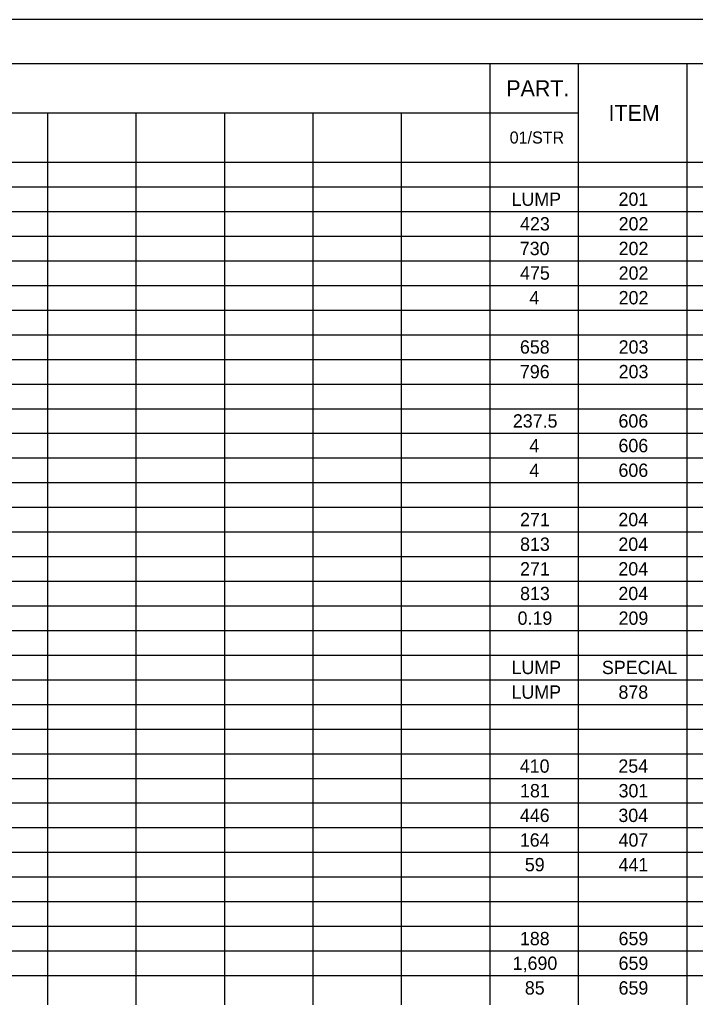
# Model space of a CAD drawing. Extents: x -98 to 34, y 0 to 58.
# Drawn here: x 9.22 to 16.9, y 10.89 to 22 of the extents above; entities that cross this region are included whole.
import ezdxf

# ---------------------------------------------------------------- set-up
doc = ezdxf.new("R2010")
doc.units = 0
for name, color, linetype in [('Default', 7, 'Continuous'), ('SH_Border', 7, 'Continuous'), ('SH_Cut_Line', 7, 'Continuous')]:
    doc.layers.add(name, color=color, linetype=linetype)

msp = doc.modelspace()

# ---------------------------------------------------------------- linework, layer by layer
at = {"layer": 'Default'}
for p, q in [((1.5, 21.5), (32, 21.5)), ((14.56, 21.5), (14.56, 0.502)), ((15.564, 21.5), (15.564, 0.502)), ((16.799, 21.5), (16.799, 0.502)), ((1.5, 20.94), (15.564, 20.94)), ((9.537, 20.94), (9.537, 0.502)), ((10.541, 20.94), (10.541, 0.502)), ((11.546, 20.94), (11.546, 0.502)), ((12.55, 20.94), (12.55, 0.502)), ((13.555, 20.94), (13.555, 0.502)), ((1.5, 20.38), (32, 20.38)), ((1.5, 20.1), (32, 20.1)), ((1.5, 19.82), (32, 19.82)), ((1.5, 19.54), (32, 19.54)), ((1.5, 19.26), (32, 19.26)), ((1.5, 18.98), (32, 18.98)), ((1.5, 18.7), (32, 18.7)), ((1.5, 18.42), (32, 18.42)), ((1.5, 18.14), (32, 18.14)), ((1.5, 17.86), (32, 17.86)), ((1.5, 17.58), (32, 17.58)), ((1.5, 17.3), (32, 17.3)), ((1.5, 17.021), (32, 17.021)), ((1.5, 16.741), (32, 16.741)), ((1.5, 16.461), (32, 16.461)), ((1.5, 16.181), (32, 16.181)), ((1.5, 15.901), (32, 15.901)), ((1.5, 15.621), (32, 15.621)), ((1.5, 15.341), (32, 15.341)), ((1.5, 15.061), (32, 15.061)), ((1.5, 14.781), (32, 14.781)), ((1.5, 14.501), (32, 14.501)), ((1.5, 14.221), (32, 14.221)), ((1.5, 13.941), (32, 13.941)), ((1.5, 13.661), (32, 13.661)), ((1.5, 13.381), (32, 13.381)), ((1.5, 13.101), (32, 13.101)), ((1.5, 12.821), (32, 12.821)), ((1.5, 12.541), (32, 12.541)), ((1.5, 12.261), (32, 12.261)), ((1.5, 11.981), (32, 11.981)), ((1.5, 11.701), (32, 11.701)), ((1.5, 11.421), (32, 11.421)), ((1.5, 11.141), (32, 11.141))]:
    msp.add_line(p, q, dxfattribs=at)
at = {"layer": 'SH_Border'}
msp.add_lwpolyline([(1.5, 21.5), (33.5, 21.5), (33.5, 0.5), (1.5, 0.5)], close=True, dxfattribs=at)
at = {"layer": 'SH_Cut_Line'}
msp.add_lwpolyline([(0, 0), (34, 0), (34, 22), (0, 22)], close=True, dxfattribs=at)

# ---------------------------------------------------------------- texts
at = {"layer": 'Default'}
for s, height, p in [('PART.', 0.1818, (14.749, 21.129)), ('ITEM', 0.1818, (15.91, 20.849)), ('01/STR', 0.1364, (14.787, 20.592)), ('LUMP', 0.1515, (14.808, 19.884)), ('201', 0.1515, (16.024, 19.884)), ('423', 0.1515, (14.905, 19.604)), ('202', 0.1515, (16.025, 19.604)), ('730', 0.1515, (14.902, 19.324)), ('202', 0.1515, (16.025, 19.324)), ('475', 0.1515, (14.905, 19.045)), ('202', 0.1515, (16.025, 19.045)), ('4', 0.152, (15.011, 18.765)), ('202', 0.1515, (16.025, 18.765)), ('658', 0.1515, (14.903, 18.205)), ('203', 0.1515, (16.025, 18.205)), ('796', 0.1515, (14.903, 17.925)), ('203', 0.1515, (16.025, 17.925)), ('237.5', 0.1515, (14.823, 17.365)), ('606', 0.1515, (16.023, 17.365)), ('4', 0.152, (15.011, 17.085)), ('606', 0.1515, (16.023, 17.085)), ('4', 0.152, (15.011, 16.805)), ('606', 0.1515, (16.023, 16.805)), ('271', 0.1515, (14.905, 16.245)), ('204', 0.1515, (16.022, 16.245)), ('813', 0.1515, (14.905, 15.965)), ('204', 0.1515, (16.022, 15.965)), ('271', 0.1515, (14.905, 15.685)), ('204', 0.1515, (16.022, 15.685)), ('813', 0.1515, (14.905, 15.405)), ('204', 0.1515, (16.022, 15.405)), ('0.19', 0.1515, (14.877, 15.125)), ('209', 0.1515, (16.024, 15.125)), ('LUMP', 0.1515, (14.808, 14.565)), ('SPECIAL', 0.1515, (15.835, 14.565)), ('LUMP', 0.1515, (14.808, 14.285)), ('878', 0.1515, (16.023, 14.285)), ('410', 0.1515, (14.902, 13.445)), ('254', 0.1515, (16.022, 13.445)), ('181', 0.1515, (14.905, 13.165)), ('301', 0.1515, (16.024, 13.165)), ('446', 0.1515, (14.903, 12.885)), ('304', 0.1515, (16.022, 12.885)), ('164', 0.1515, (14.902, 12.605)), ('407', 0.1515, (16.024, 12.605)), ('59', 0.1515, (14.959, 12.325)), ('441', 0.1515, (16.024, 12.325)), ('188', 0.1515, (14.903, 11.485)), ('659', 0.1515, (16.024, 11.485)), ('1,690', 0.1515, (14.821, 11.205)), ('659', 0.1515, (16.024, 11.205)), ('85', 0.1515, (14.959, 10.925)), ('659', 0.1515, (16.024, 10.925))]:
    msp.add_text(s, height=height, dxfattribs=at).set_placement(p)

doc.saveas('drawing.dxf')
